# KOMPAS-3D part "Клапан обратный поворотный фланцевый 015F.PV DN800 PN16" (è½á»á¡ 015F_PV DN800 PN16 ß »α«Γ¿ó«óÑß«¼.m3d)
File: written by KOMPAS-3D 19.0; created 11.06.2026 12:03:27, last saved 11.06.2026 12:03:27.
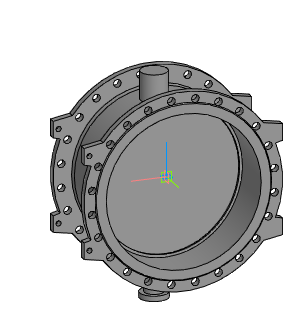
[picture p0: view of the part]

Document properties: Автор: Энергия; Полное имя файла: Z:\3.Личные\kachalov\001_3d для проектировщиков\5.5 Тип 015F.PV Клапан обратный поворотный с двумя эксцентриками\_stp_Клапан 015F.PV DN300-DN1200 с противовесом\Клапан 015F_PV DN800 PN16 с противовесом.m3d

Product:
- Part/product: Клапан обратный поворотный фланцевый 015F.PV DN800 PN16

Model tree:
1. Операция без истории:1
2. Сплайн:1
     Координата Y = 30; Координата Z = 400; Вес = 1; Координата X = 800; Координата Y = 135.322; Координата Z = 400; Вес = 0.333333; Координата X = 800; Координата Y = 135.322; Координата Z = -400; Вес = 0.333333; Координата Y = 30; Координата Z = -400; Вес = 1; Координата X = -800; Координата Y = -75.322; Координата Z = -400; Вес = 0.333333; Координата X = -800; Координата Y = -75.322; Координата Z = 400; Вес = 0.333333; Порядок = 4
